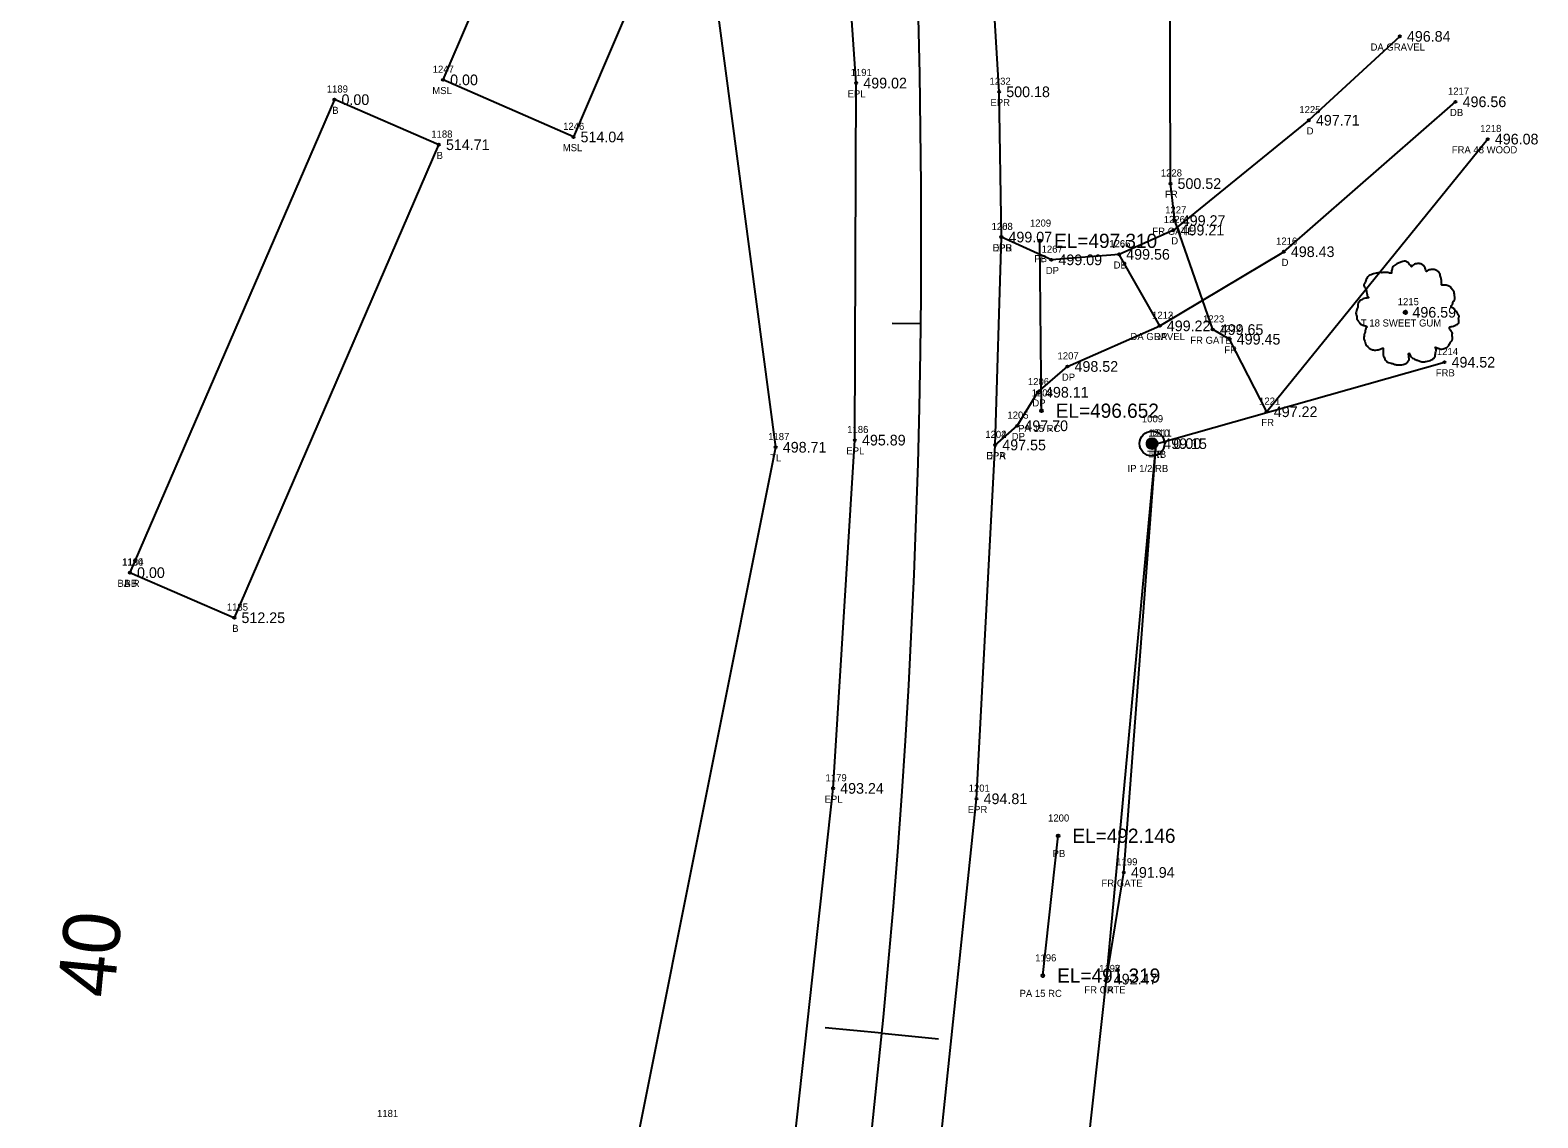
# Model space of a CAD drawing. Extents: x 1649047 to 1650429, y 896228 to 898747.
# Drawn here: x 1649819 to 1650031.1, y 897668 to 897821 of the extents above; entities that cross this region are included whole.
import ezdxf

# ---------------------------------------------------------------- set-up
doc = ezdxf.new("R2010")
doc.units = 0
for name, color, linetype in [('RD_EX_Bldg', 7, 'Continuous'), ('RD_EX_Bldg_txCode', 7, 'Continuous'), ('RD_EX_DR_Pipe', 7, 'Continuous'), ('RD_EX_DR_Pipe_txCode', 7, 'Continuous'), ('RD_EX_Driveway', 7, 'Continuous'), ('RD_EX_Driveway_txCode', 7, 'Continuous'), ('RD_EX_DV_Prop_txCode', 7, 'Continuous'), ('RD_EX_DV_PropPin', 7, 'Continuous'), ('RD_EX_Fence_Other', 7, 'Continuous'), ('RD_EX_Fence_Other_txCode', 7, 'Continuous'), ('RD_EX_Misc', 7, 'Continuous'), ('RD_EX_Misc_txCode', 7, 'Continuous'), ('RD_EX_Road', 7, 'Continuous'), ('RD_EX_Road_txCode', 7, 'Continuous'), ('RD_EX_TX_Bldg_ELEV', 7, 'Continuous'), ('RD_EX_TX_Driveway_ELEV', 7, 'Continuous'), ('RD_EX_TX_DV_Prop_ELEV', 7, 'Continuous'), ('RD_EX_TX_Fence_Other_ELEV', 7, 'Continuous'), ('RD_EX_TX_Misc_ELEV', 7, 'Continuous'), ('RD_EX_TX_Road_ELEV', 7, 'Continuous'), ('RD_EX_TX_VEG_ELEV', 7, 'Continuous'), ('RD_EX_VEG', 7, 'Continuous'), ('RD_EX_VEG_txCode', 7, 'Continuous'), ('RD_HC_Cl', 7, 'Continuous'), ('RD_HC_Data_Tic', 7, 'Continuous'), ('RD_HC_TX_Sta50', 7, 'Continuous'), ('RD_SMD_Locator', 7, 'Continuous'), ('RD_TX_Pipe_ElevEX', 7, 'Continuous')]:
    doc.layers.add(name, color=color, linetype=linetype)

msp = doc.modelspace()

# ---------------------------------------------------------------- linework, layer by layer
at = {"layer": 'RD_EX_Bldg'}
msp.add_lwpolyline([(1649833.07, 897744.68), (1649847.76, 897738.34), (1649876.52, 897804.87), (1649861.83, 897811.21), (1649833.07, 897744.68)], dxfattribs=at)
at = {"layer": 'RD_EX_DR_Pipe'}
for p, q in [((1649961.29, 897767.46), (1649961.05, 897791.35)), ((1649961.49, 897688), (1649963.63, 897707.67))]:
    msp.add_line(p, q, dxfattribs=at)
at = {"layer": 'RD_EX_Driveway'}
for points in [[(1650011.68, 897820.11), (1649998.89, 897808.31), (1649979.85, 897792.86), (1649972.2, 897789.45)], [(1649977.91, 897779.39), (1649995.36, 897789.82), (1650019.52, 897810.91)], [(1649954.77, 897762.63), (1649957.88, 897765.34), (1649960.78, 897770.05), (1649964.93, 897773.68), (1649977.91, 897779.39), (1649972.2, 897789.45), (1649962.67, 897788.68), (1649955.64, 897791.88)]]:
    msp.add_lwpolyline(points, dxfattribs=at)
at = {"layer": 'RD_EX_DV_PropPin'}
for p, q in [((1649976.1, 897762.63), (1649976.1, 897763.03)), ((1649976.14, 897762.53), (1649976.14, 897763.13)), ((1649976.17, 897762.46), (1649976.17, 897763.2)), ((1649976.21, 897762.4), (1649976.21, 897763.26)), ((1649976.24, 897762.35), (1649976.24, 897763.3)), ((1649976.28, 897762.31), (1649976.28, 897763.34)), ((1649976.31, 897762.28), (1649976.31, 897763.38)), ((1649976.35, 897762.25), (1649976.35, 897763.41)), ((1649976.38, 897762.22), (1649976.38, 897763.44)), ((1649976.42, 897762.19), (1649976.42, 897763.46)), ((1649976.45, 897762.17), (1649976.45, 897763.49)), ((1649976.49, 897762.15), (1649976.49, 897763.5)), ((1649976.52, 897762.14), (1649976.52, 897763.52)), ((1649976.56, 897762.12), (1649976.56, 897763.54)), ((1649976.59, 897762.11), (1649976.59, 897763.55)), ((1649976.63, 897762.1), (1649976.63, 897763.56)), ((1649976.66, 897762.09), (1649976.66, 897763.57)), ((1649976.7, 897762.08), (1649976.7, 897763.58)), ((1649976.73, 897762.08), (1649976.73, 897763.58)), ((1649976.77, 897762.07), (1649976.77, 897763.59)), ((1649976.8, 897762.07), (1649976.8, 897763.59)), ((1649976.84, 897762.07), (1649976.84, 897763.59)), ((1649976.87, 897762.07), (1649976.87, 897763.59)), ((1649976.91, 897762.07), (1649976.91, 897763.59)), ((1649976.94, 897762.08), (1649976.94, 897763.58)), ((1649976.98, 897762.08), (1649976.98, 897763.58)), ((1649977.01, 897762.09), (1649977.01, 897763.57)), ((1649977.05, 897762.1), (1649977.05, 897763.56)), ((1649977.08, 897762.11), (1649977.08, 897763.55)), ((1649977.12, 897762.12), (1649977.12, 897763.54)), ((1649977.15, 897762.14), (1649977.15, 897763.52)), ((1649977.19, 897762.15), (1649977.19, 897763.5)), ((1649977.22, 897762.17), (1649977.22, 897763.49)), ((1649977.26, 897762.19), (1649977.26, 897763.46)), ((1649977.29, 897762.22), (1649977.29, 897763.44)), ((1649977.33, 897762.25), (1649977.33, 897763.41)), ((1649977.36, 897762.28), (1649977.36, 897763.38)), ((1649977.4, 897762.31), (1649977.4, 897763.34)), ((1649977.43, 897762.35), (1649977.43, 897763.3)), ((1649977.47, 897762.4), (1649977.47, 897763.26)), ((1649977.5, 897762.46), (1649977.5, 897763.2)), ((1649977.54, 897762.53), (1649977.54, 897763.13)), ((1649977.57, 897762.63), (1649977.57, 897763.03))]:
    msp.add_line(p, q, dxfattribs=at)
for radius in [1.75, 0.761]:
    msp.add_circle((1649976.84, 897762.83), radius, dxfattribs=at)
at = {"layer": 'RD_EX_Fence_Other'}
for points in [[(1650024.05, 897805.66), (1649992.96, 897767.31), (1649987.75, 897777.51), (1649985.36, 897778.87), (1649980.02, 897794.2), (1649979.42, 897799.4), (1649979.28, 897850.56), (1649966.51, 897963.69), (1649940.2, 898118.22), (1649931.13, 898165.01)], [(1649933.32, 897463.99), (1649952.37, 897560.4), (1649962.02, 897611.35), (1649970.45, 897687.51), (1649972.87, 897702.51), (1649977.41, 897762.82), (1650017.96, 897774.28)]]:
    msp.add_lwpolyline(points, dxfattribs=at)
at = {"layer": 'RD_EX_Misc'}
msp.add_lwpolyline([(1649884.54, 897831.31), (1649902.89, 897823.28), (1649895.45, 897805.96), (1649877.11, 897813.99), (1649884.54, 897831.31)], dxfattribs=at)
at = {"layer": 'RD_EX_Road'}
for points in [[(1649905.13, 897459.2), (1649918.81, 897511.88), (1649930.39, 897563.05), (1649939.7, 897612.37), (1649946.83, 897662.25), (1649952.14, 897712.87), (1649954.77, 897762.63), (1649955.64, 897791.88), (1649955.33, 897812.31), (1649952.46, 897859.75), (1649947.95, 897909.71), (1649941.78, 897959.51), (1649933.15, 898009.23), (1649924.03, 898060.85), (1649913.91, 898112.48), (1649904.76, 898159.93)], [(1649885.84, 897465.29), (1649899.42, 897516.76), (1649910.69, 897567.43), (1649919.68, 897616.11), (1649926.54, 897664.67), (1649931.97, 897714.33), (1649935.04, 897763.32), (1649935.22, 897813.54), (1649932.16, 897857.76), (1649927.73, 897907.79), (1649922.24, 897954.81), (1649913.41, 898005.06), (1649903.99, 898056.19), (1649899.68, 898079.2), (1649896.48, 898096.53), (1649894.5, 898108.47), (1649884.77, 898155.82)]]:
    msp.add_lwpolyline(points, dxfattribs=at)
at = {"layer": 'RD_EX_VEG'}
for points in [[(1649617.18, 897070.52), (1649712.19, 897191.88), (1649745.96, 897241.38), (1649814.66, 897340.98), (1649833.89, 897382.46), (1649865.2, 897454.4), (1649884.45, 897522.02), (1649904.5, 897665.19), (1649923.9, 897762.32), (1649882.75, 898072.18)], [(1649928.51, 897459.07), (1649952.37, 897560.4), (1649962.02, 897611.35), (1649970.45, 897687.51), (1649977.41, 897762.82)]]:
    msp.add_lwpolyline(points, dxfattribs=at)
for centre, radius in [((1650012.46, 897781.3), 0.25), ((1650012.44, 897781.28), 0.0001)]:
    msp.add_circle(centre, radius, dxfattribs=at)
for points in [[(1650012.59, 897788.46), (1650012.29, 897788.49), (1650011.96, 897788.39), (1650011.71, 897788.29), (1650011.49, 897788.21), (1650011.26, 897788.11), (1650010.97, 897787.94), (1650010.74, 897787.74), (1650010.62, 897787.49), (1650010.57, 897787.26), (1650010.52, 897786.99), (1650010.52, 897786.82), (1650010.39, 897786.79), (1650010.24, 897786.82), (1650009.99, 897786.89), (1650009.74, 897786.89), (1650009.49, 897786.89), (1650009.14, 897786.87), (1650008.79, 897786.87), (1650008.52, 897786.82), (1650008.19, 897786.77), (1650007.82, 897786.64), (1650007.47, 897786.52), (1650007.17, 897786.27), (1650006.92, 897785.79), (1650006.79, 897785.44), (1650006.64, 897785.19), (1650006.79, 897784.74), (1650006.97, 897784.39), (1650006.99, 897784.19), (1650007.07, 897783.77), (1650007.17, 897783.54), (1650007.29, 897783.34), (1650007.22, 897783.32), (1650006.84, 897783.27), (1650006.54, 897783.17), (1650006.12, 897782.94), (1650005.89, 897782.72), (1650005.79, 897782.39), (1650005.77, 897782.04), (1650005.67, 897781.84), (1650005.59, 897781.57), (1650005.57, 897781.49), (1650005.52, 897781.17), (1650005.62, 897780.72), (1650005.64, 897780.37), (1650005.77, 897780.14), (1650005.92, 897779.97), (1650006.09, 897779.72), (1650006.49, 897779.49), (1650006.82, 897779.39), (1650007.02, 897779.37), (1650006.84, 897778.87), (1650006.79, 897778.52), (1650006.67, 897778.12), (1650006.67, 897778.04), (1650006.62, 897777.57), (1650006.77, 897777.24), (1650006.84, 897776.87), (1650007.02, 897776.64), (1650007.29, 897776.34), (1650007.62, 897776.12), (1650008.12, 897775.99), (1650008.52, 897776.02), (1650009.09, 897776.19), (1650009.34, 897776.27), (1650009.32, 897776.09), (1650009.34, 897775.72), (1650009.34, 897775.3), (1650009.49, 897774.97), (1650009.59, 897774.7), (1650009.74, 897774.45), (1650010.07, 897774.22), (1650010.47, 897774.15), (1650010.89, 897774), (1650011.34, 897773.92), (1650011.84, 897773.9), (1650012.44, 897774.05), (1650012.71, 897774.17), (1650012.81, 897774.35), (1650013.01, 897774.72), (1650012.96, 897774.95), (1650012.99, 897775.55), (1650013.09, 897775.37), (1650013.26, 897775.02), (1650013.76, 897774.72), (1650014.16, 897774.55), (1650014.64, 897774.4), (1650014.94, 897774.32), (1650015.41, 897774.4), (1650015.79, 897774.47), (1650016.16, 897774.6), (1650016.46, 897774.87), (1650016.64, 897775.15), (1650016.69, 897775.42), (1650016.76, 897775.79), (1650016.81, 897775.97)], [(1650016.81, 897775.97), (1650016.74, 897776.14), (1650016.69, 897776.39), (1650016.76, 897776.37), (1650016.94, 897776.32), (1650017.21, 897776.19), (1650017.44, 897776.12), (1650017.76, 897776.14), (1650018.04, 897776.24), (1650018.49, 897776.52), (1650018.76, 897776.99), (1650019.04, 897777.39), (1650019.11, 897777.72), (1650019.06, 897777.94), (1650019.04, 897778.44), (1650018.84, 897778.69), (1650018.79, 897778.82), (1650018.69, 897779.22), (1650018.76, 897779.27), (1650019.04, 897779.32), (1650019.41, 897779.44), (1650019.69, 897779.57), (1650019.91, 897779.74), (1650019.99, 897779.97), (1650019.96, 897780.37), (1650020.01, 897780.77), (1650019.94, 897780.92), (1650019.84, 897781.07), (1650019.76, 897781.27), (1650019.61, 897781.42), (1650019.51, 897781.57), (1650019.41, 897781.67), (1650019.29, 897781.82), (1650019.11, 897781.94), (1650018.96, 897781.99), (1650018.91, 897782.14), (1650019.06, 897782.34), (1650019.11, 897782.44), (1650019.14, 897782.67), (1650019.36, 897783.02), (1650019.41, 897783.42), (1650019.36, 897783.84), (1650019.31, 897784.12), (1650019.16, 897784.39), (1650018.96, 897784.64), (1650018.84, 897784.82), (1650018.66, 897784.94), (1650018.34, 897785.07), (1650018.09, 897785.12), (1650017.74, 897785.12), (1650017.54, 897785.17), (1650017.56, 897785.22), (1650017.56, 897785.37), (1650017.56, 897785.64), (1650017.49, 897786.09), (1650017.34, 897786.59), (1650017.34, 897786.62), (1650017.24, 897786.87), (1650017.01, 897787.06), (1650016.84, 897787.16), (1650016.64, 897787.29), (1650016.39, 897787.31), (1650016.09, 897787.31), (1650015.81, 897787.26), (1650015.61, 897787.16), (1650015.44, 897787.04), (1650015.36, 897787.19), (1650015.26, 897787.49), (1650015.21, 897787.64), (1650015.06, 897787.81), (1650014.84, 897788.01), (1650014.39, 897788.14), (1650013.76, 897788.06), (1650013.46, 897787.86), (1650013.31, 897787.69), (1650013.26, 897787.81), (1650013.06, 897788.01), (1650012.96, 897788.19), (1650012.79, 897788.31), (1650012.64, 897788.41), (1650012.54, 897788.46)]]:
    msp.add_spline(points, degree=3, dxfattribs=at)
at = {"layer": 'RD_HC_Cl'}
msp.add_arc((1648799.37, 897792.37), 1145, 320.82481, 10.99954, dxfattribs=at)
at = {"layer": 'RD_HC_Data_Tic'}
for p, q in [((1649944.3, 897779.7), (1649940.3, 897779.74)), ((1649938.83, 897679.88), (1649930.87, 897680.66)), ((1649938.83, 897679.88), (1649946.79, 897679.09))]:
    msp.add_line(p, q, dxfattribs=at)
at = {"layer": 'RD_SMD_Locator'}
for centre, radius in [((1650011.68, 897820.11), 0.15), ((1649877.11, 897813.99), 0.15), ((1649935.22, 897813.54), 0.15), ((1649955.33, 897812.31), 0.15), ((1649861.83, 897811.21), 0.15), ((1650019.52, 897810.91), 0.15), ((1649998.89, 897808.31), 0.15), ((1649895.45, 897805.96), 0.15), ((1650024.05, 897805.66), 0.15), ((1649876.52, 897804.87), 0.15), ((1649979.42, 897799.4), 0.15), ((1649979.85, 897792.86), 0.15), ((1649980.02, 897794.2), 0.15), ((1649955.64, 897791.88), 0.15), ((1649955.64, 897791.88), 0.15), ((1649961.05, 897791.35), 0.2), ((1649962.67, 897788.68), 0.15), ((1649972.2, 897789.45), 0.15), ((1649972.2, 897789.45), 0.15), ((1649995.36, 897789.82), 0.15), ((1650012.46, 897781.3), 0.15), ((1649977.91, 897779.39), 0.15), ((1649977.91, 897779.39), 0.15), ((1649985.36, 897778.87), 0.15), ((1649987.75, 897777.51), 0.15), ((1649964.93, 897773.68), 0.15), ((1650017.96, 897774.28), 0.15), ((1649960.78, 897770.05), 0.15), ((1649961.29, 897767.46), 0.2), ((1649992.96, 897767.31), 0.15), ((1649957.88, 897765.34), 0.15), ((1649935.04, 897763.32), 0.15), ((1649923.9, 897762.32), 0.15), ((1649954.77, 897762.63), 0.15), ((1649954.77, 897762.63), 0.15), ((1649976.84, 897762.83), 0.15), ((1649977.41, 897762.82), 0.15), ((1649977.41, 897762.82), 0.15), ((1649833.07, 897744.68), 0.15), ((1649833.07, 897744.68), 0.15), ((1649847.76, 897738.34), 0.15), ((1649931.97, 897714.33), 0.15), ((1649952.14, 897712.87), 0.15), ((1649963.63, 897707.67), 0.2), ((1649972.87, 897702.51), 0.15), ((1649961.49, 897688), 0.2), ((1649970.45, 897687.51), 0.15), ((1649970.45, 897687.51), 0.15)]:
    msp.add_circle(centre, radius, dxfattribs=at)

# ---------------------------------------------------------------- texts
at = {"layer": 'RD_EX_Bldg_txCode'}
for s, p in [('1189', (1649860.76, 897812.21)), ('B', (1649861.52, 897809.21)), ('1188', (1649875.46, 897805.87)), ('B', (1649876.21, 897802.87)), ('1190', (1649831.96, 897745.68)), ('1184', (1649832, 897745.68)), ('BA R', (1649831.31, 897742.68)), ('BB', (1649832.29, 897742.68)), ('1185', (1649846.7, 897739.34)), ('B', (1649847.45, 897736.34))]:
    msp.add_text(s, height=1, dxfattribs=at).set_placement(p)
at = {"layer": 'RD_EX_DR_Pipe_txCode'}
for s, p in [('1209', (1649959.66, 897793.35)), ('PB', (1649960.27, 897788.35)), ('1208', (1649959.9, 897769.46)), ('PA 15 RC', (1649958, 897764.46)), ('1200', (1649962.21, 897709.67)), ('PB', (1649962.85, 897704.67)), ('1196', (1649960.4, 897690)), ('PA 15 RC', (1649958.2, 897685))]:
    msp.add_text(s, height=1, dxfattribs=at).set_placement(p)
at = {"layer": 'RD_EX_Driveway_txCode'}
for s, p in [('DA GRAVEL', (1650007.57, 897818.11)), ('1217', (1650018.46, 897811.91)), ('1225', (1649997.55, 897809.31)), ('DB', (1650018.74, 897808.91)), ('D', (1649998.58, 897806.31)), ('1226', (1649978.48, 897793.86)), ('1268', (1649954.27, 897792.88)), ('DPB', (1649954.39, 897789.88)), ('1267', (1649961.3, 897789.68)), ('1266', (1649970.81, 897790.45)), ('1265', (1649970.83, 897790.45)), ('D', (1649979.54, 897790.86)), ('1216', (1649994.28, 897790.82)), ('D', (1649995.06, 897787.82)), ('DP', (1649961.89, 897786.68)), ('DB', (1649971.43, 897787.45)), ('DP', (1649971.43, 897787.45)), ('1212', (1649976.84, 897780.39)), ('1213', (1649976.84, 897780.39)), ('DA GRAVEL', (1649973.8, 897777.39)), ('DP', (1649977.13, 897777.39)), ('1207', (1649963.54, 897774.68)), ('1206', (1649959.37, 897771.05)), ('DP', (1649964.15, 897771.68)), ('1205', (1649956.49, 897766.34)), ('DP', (1649960, 897768.05)), ('1204', (1649953.38, 897763.63)), ('DP', (1649957.1, 897763.34)), ('DPA', (1649953.5, 897760.63))]:
    msp.add_text(s, height=1, dxfattribs=at).set_placement(p)
at = {"layer": 'RD_EX_DV_Prop_txCode'}
for s, p in [('1009', (1649975.41, 897765.83)), ('IP 1/2 RB', (1649973.39, 897758.83))]:
    msp.add_text(s, height=1, dxfattribs=at).set_placement(p)
at = {"layer": 'RD_EX_Fence_Other_txCode'}
for s, p in [('1218', (1650022.99, 897806.66)), ('FRA 48 WOOD', (1650018.99, 897803.66)), ('1228', (1649978.07, 897800.4)), ('FR', (1649978.66, 897797.4)), ('1227', (1649978.68, 897795.2)), ('FR GATE', (1649976.88, 897792.2)), ('1223', (1649984.01, 897779.87)), ('FR GATE', (1649982.21, 897776.87)), ('1222', (1649986.4, 897778.51)), ('FR', (1649986.99, 897775.51)), ('1214', (1650016.9, 897775.28)), ('FRB', (1650016.74, 897772.28)), ('1221', (1649991.89, 897768.31)), ('FR', (1649992.2, 897765.31)), ('1210', (1649976.31, 897763.82)), ('FR', (1649976.66, 897760.82)), ('1199', (1649971.8, 897703.51)), ('FR GATE', (1649969.72, 897700.51)), ('1197', (1649969.39, 897688.51)), ('FR GATE', (1649967.31, 897685.51)), ('1181', (1649867.83, 897668.11))]:
    msp.add_text(s, height=1, dxfattribs=at).set_placement(p)
at = {"layer": 'RD_EX_Misc_txCode'}
for s, p in [('1247', (1649875.66, 897814.99)), ('MSL', (1649875.6, 897811.99)), ('1246', (1649894, 897806.96)), ('MSL', (1649893.95, 897803.96))]:
    msp.add_text(s, height=1, dxfattribs=at).set_placement(p)
at = {"layer": 'RD_EX_Road_txCode'}
for s, p in [('1191', (1649934.44, 897814.54)), ('1232', (1649953.98, 897813.31)), ('EPL', (1649934.01, 897811.54)), ('EPR', (1649954.1, 897810.31)), ('1203', (1649954.26, 897792.88)), ('EPR', (1649954.41, 897789.88)), ('1186', (1649933.96, 897764.32)), ('1202', (1649953.38, 897763.63)), ('EPL', (1649933.84, 897761.32)), ('EPR', (1649953.54, 897760.63)), ('1179', (1649930.91, 897715.33)), ('1201', (1649951.04, 897713.87)), ('EPL', (1649930.77, 897712.33)), ('EPR', (1649950.91, 897710.87))]:
    msp.add_text(s, height=1, dxfattribs=at).set_placement(p)
at = {"layer": 'RD_EX_TX_Bldg_ELEV'}
for s, p in [('0.00', (1649862.83, 897810.46)), ('514.71', (1649877.52, 897804.12)), ('0.00', (1649834.07, 897743.93)), ('0.00', (1649834.07, 897743.93)), ('512.25', (1649848.76, 897737.59))]:
    msp.add_text(s, height=1.5, dxfattribs=at).set_placement(p)
at = {"layer": 'RD_EX_TX_Driveway_ELEV'}
for s, p in [('496.84', (1650012.68, 897819.36)), ('496.56', (1650020.52, 897810.16)), ('497.71', (1649999.89, 897807.56)), ('499.21', (1649980.85, 897792.11)), ('499.07', (1649956.64, 897791.13)), ('498.43', (1649996.36, 897789.07)), ('499.09', (1649963.67, 897787.93)), ('499.56', (1649973.2, 897788.7)), ('499.56', (1649973.2, 897788.7)), ('499.22', (1649978.91, 897778.64)), ('499.22', (1649978.91, 897778.64)), ('498.52', (1649965.93, 897772.93)), ('498.11', (1649961.78, 897769.3)), ('497.70', (1649958.88, 897764.59)), ('497.55', (1649955.77, 897761.88))]:
    msp.add_text(s, height=1.5, dxfattribs=at).set_placement(p)
at = {"layer": 'RD_EX_TX_DV_Prop_ELEV'}
msp.add_text('0.00', height=1.5, dxfattribs=at).set_placement((1649979.84, 897762.08))
at = {"layer": 'RD_EX_TX_Fence_Other_ELEV'}
for s, p in [('496.08', (1650025.05, 897804.91)), ('500.52', (1649980.42, 897798.65)), ('499.27', (1649981.02, 897793.45)), ('499.65', (1649986.36, 897778.12)), ('499.45', (1649988.75, 897776.76)), ('494.52', (1650018.96, 897773.53)), ('497.22', (1649993.96, 897766.56)), ('499.15', (1649978.41, 897762.07)), ('491.94', (1649973.87, 897701.76)), ('492.47', (1649971.45, 897686.76))]:
    msp.add_text(s, height=1.5, dxfattribs=at).set_placement(p)
at = {"layer": 'RD_EX_TX_Misc_ELEV'}
for s, p in [('0.00', (1649878.11, 897813.24)), ('514.04', (1649896.45, 897805.21))]:
    msp.add_text(s, height=1.5, dxfattribs=at).set_placement(p)
at = {"layer": 'RD_EX_TX_Road_ELEV'}
for s, p in [('499.02', (1649936.22, 897812.79)), ('500.18', (1649956.33, 897811.56)), ('499.07', (1649956.64, 897791.13)), ('495.89', (1649936.04, 897762.57)), ('497.55', (1649955.77, 897761.88)), ('493.24', (1649932.97, 897713.58)), ('494.81', (1649953.14, 897712.12))]:
    msp.add_text(s, height=1.5, dxfattribs=at).set_placement(p)
at = {"layer": 'RD_EX_TX_VEG_ELEV'}
for s, p in [('496.59', (1650013.46, 897780.55)), ('498.71', (1649924.9, 897761.57)), ('499.15', (1649978.41, 897762.07)), ('492.47', (1649971.45, 897686.76))]:
    msp.add_text(s, height=1.5, dxfattribs=at).set_placement(p)
at = {"layer": 'RD_EX_VEG_txCode'}
for s, p in [('1215', (1650011.39, 897782.3)), ('T 18 SWEET GUM', (1650006.21, 897779.3)), ('1187', (1649922.84, 897763.32)), ('1211', (1649976.63, 897763.82)), ('TL', (1649923.13, 897760.32)), ('TRB', (1649976.14, 897760.82)), ('1198', (1649969.39, 897688.51)), ('TR', (1649969.66, 897685.51))]:
    msp.add_text(s, height=1, dxfattribs=at).set_placement(p)
at = {"layer": 'RD_HC_TX_Sta50'}
msp.add_text('40', height=8, rotation=84.3617, dxfattribs=at).set_placement((1649830.78, 897684.72))
at = {"layer": 'RD_TX_Pipe_ElevEX'}
for s, p in [('EL=497.310', (1649963.05, 897790.35)), ('EL=496.652', (1649963.29, 897766.46)), ('EL=492.146', (1649965.63, 897706.67)), ('EL=491.319', (1649963.49, 897687))]:
    msp.add_text(s, height=2, dxfattribs=at).set_placement(p)

doc.saveas('drawing.dxf')
